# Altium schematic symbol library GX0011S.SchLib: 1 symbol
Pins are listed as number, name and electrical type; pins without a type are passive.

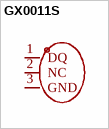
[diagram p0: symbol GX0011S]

## GX0011S
designator U?  (value not drawn)
footprint TO-92S-3_L4.0-W1.5-P1.27-L
pins: 1 DQ, 2 NC, 3 GND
